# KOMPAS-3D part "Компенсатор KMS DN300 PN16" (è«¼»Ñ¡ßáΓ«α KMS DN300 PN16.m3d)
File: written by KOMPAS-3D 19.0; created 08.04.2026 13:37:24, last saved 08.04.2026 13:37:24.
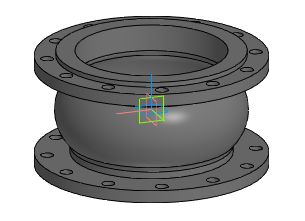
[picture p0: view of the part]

Document properties: Автор: Энергия; Полное имя файла: Z:\3.Личные\kachalov\3d для проектировщиков\7.1 Компенсатор\stp_Компенсатор KSM\Компенсатор KMS DN300 PN16.m3d

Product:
- Part/product: Компенсатор KMS DN300 PN16

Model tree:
1. Операция без истории:1  (labels: Компенсатор KMS DN300 PN16)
